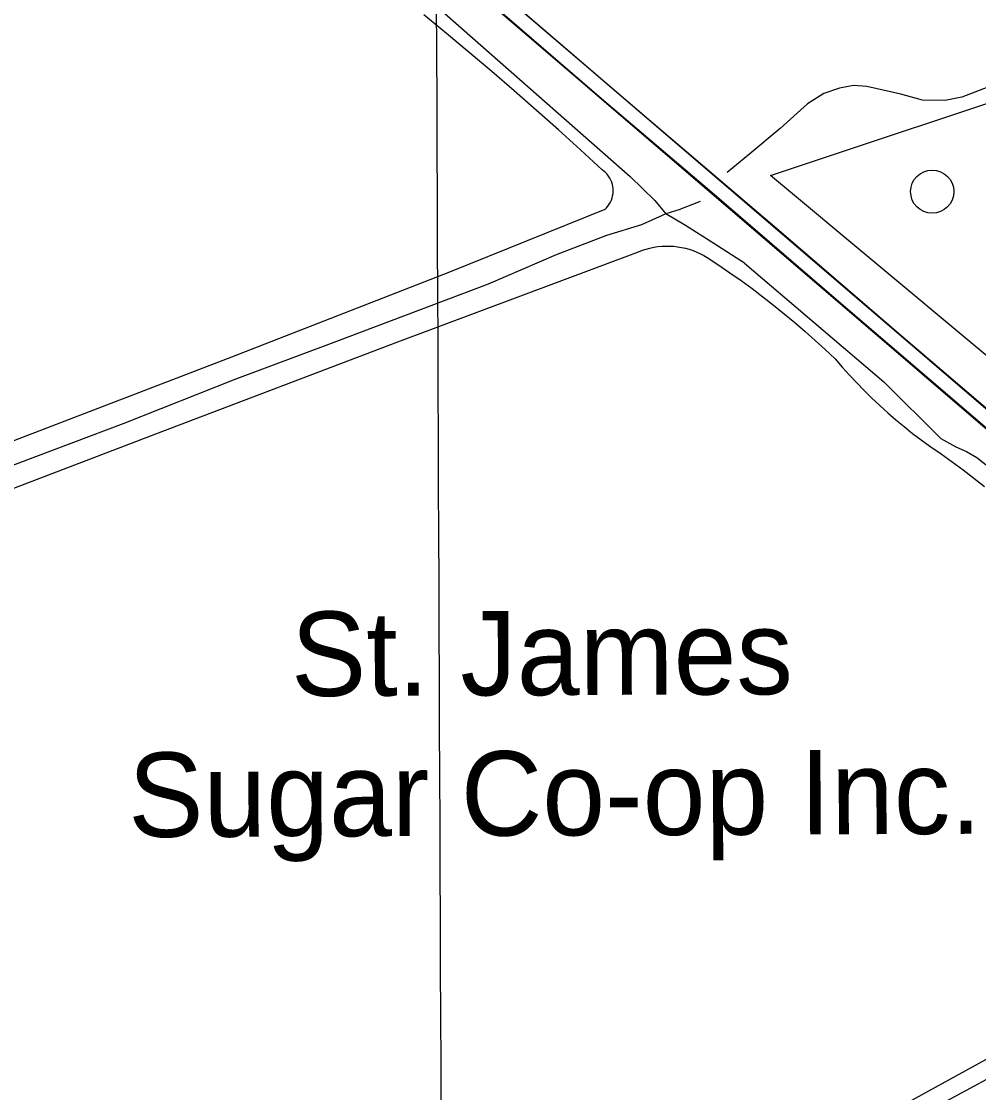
# Model space of a CAD drawing. Extents: x 3424494 to 3462436, y 522220 to 547718.
# Drawn here: x 3433422 to 3434363, y 542993 to 544046 of the extents above; entities that cross this region are included whole.
import ezdxf

# ---------------------------------------------------------------- set-up
doc = ezdxf.new("R2010")
doc.units = 0
for name, color, linetype in [('V-BLDG-IDEN', 7, 'Continuous'), ('V-DOMW-TANK', 7, 'Continuous'), ('V-DTCH-CNTR', 7, 'Continuous'), ('V-GRID-MAJR', 7, 'Continuous'), ('V-RAIL-TRAK', 7, 'Continuous'), ('V-ROAD-CNTR', 7, 'Continuous'), ('V-SITE-OTLN', 7, 'Continuous'), ('V-TOPO-SHOR', 7, 'Continuous')]:
    doc.layers.add(name, color=color, linetype=linetype)

msp = doc.modelspace()

# ---------------------------------------------------------------- linework, layer by layer
at = {"layer": 'V-DOMW-TANK'}
msp.add_circle((3434317.871326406, 543879.037215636), 21.243559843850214, dxfattribs=at)
at = {"layer": 'V-DTCH-CNTR'}
for points in [[(3433996.107, 543861.47), (3433997.694, 543863.066), (3433999.136, 543864.796), (3434000.414, 543866.652), (3434001.522, 543868.612), (3434002.448, 543870.664), (3434003.187, 543872.789), (3434003.732, 543874.975), (3434004.08, 543877.201), (3434004.225, 543879.448), (3434004.17, 543881.698), (3434003.912, 543883.935), (3434003.453, 543886.14), (3434002.8000000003, 543888.295), (3434001.9560000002, 543890.382), (3434000.928, 543892.385), (3433999.724, 543894.287), (3433998.3540000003, 543896.075), (3433996.828, 543897.732), (3433995.161, 543899.248), (3433993.365, 543900.605), (3433971.955, 543920.213), (3433950.4, 543939.665), (3433928.703, 543958.957), (3433906.865, 543978.089), (3433884.8880000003, 543997.06), (3433862.772, 544015.871), (3433840.518, 544034.518), (3433818.13, 544053.001)], [(3433996.107, 543861.47), (3433843.234, 543799.909), (3433628.991, 543716.373), (3433370.009, 543617.091)], [(3433339.258, 543558.526), (3433561.611, 543643.596), (3433792.472, 543731.187), (3434029.2660000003, 543819.929), (3434032.918, 543821.336), (3434036.639, 543822.546), (3434040.42, 543823.556), (3434044.247, 543824.365), (3434048.114, 543824.969), (3434052.005, 543825.366), (3434055.915, 543825.554), (3434059.826, 543825.536), (3434063.734, 543825.311), (3434067.6210000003, 543824.877), (3434071.482, 543824.238), (3434075.301, 543823.394), (3434079.071, 543822.3470000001), (3434082.7800000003, 543821.102), (3434086.42, 543819.66), (3434089.975, 543818.028), (3434093.438, 543816.209), (3434096.803, 543814.211), (3434107.969, 543806.825), (3434119.018, 543799.2660000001), (3434129.946, 543791.533), (3434140.751, 543783.632), (3434151.433, 543775.561), (3434161.987, 543767.322), (3434172.411, 543758.921), (3434182.7, 543750.356), (3434192.8540000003, 543741.629), (3434202.8710000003, 543732.745), (3434212.7460000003, 543723.705), (3434222.4790000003, 543714.514), (3434229.411, 543706.531), (3434236.4990000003, 543698.689), (3434243.745, 543690.991), (3434251.14, 543683.438), (3434258.687, 543676.034), (3434266.379, 543668.782), (3434274.217, 543661.688), (3434282.194, 543654.7490000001), (3434290.306, 543647.9720000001), (3434298.556, 543641.359), (3434306.934, 543634.912), (3434315.4390000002, 543628.635), (3434326.552, 543621.172), (3434337.504, 543613.474), (3434348.289, 543605.546), (3434358.906, 543597.3910000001), (3434369.347, 543589.012)], [(3434514.9620000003, 543104.937), (3434314.397, 542994.453), (3434178.242, 542919.759)]]:
    msp.add_lwpolyline(points, dxfattribs=at)
at = {"layer": 'V-GRID-MAJR'}
msp.add_spline([(3433899.984, 527634.123), (3433874.427, 533693.136), (3433848.862, 539754.083), (3433823.2970000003, 545815.045), (3433823.289, 545816.963)], degree=3, dxfattribs=at)
at = {"layer": 'V-RAIL-TRAK'}
for points in [[(3433283.139, 544579.546), (3433433.097, 544451.309), (3433542.3680000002, 544357.2710000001), (3433704.515, 544218.8910000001), (3433864.492, 544081.313), (3433992.629, 543970.577), (3434099.355, 543880.109), (3434230.64, 543767.184), (3434365.071, 543652.068), (3434485.35, 543548.884), (3434638.849, 543418.058), (3434810.4220000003, 543270.3420000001), (3434948.98, 543151.449), (3435062.972, 543054.028), (3435154.165, 542975.696)], [(3435190.421, 542962.13), (3435035.748, 543094.74), (3434892.873, 543218.593), (3434779.864, 543315.615), (3434627.745, 543445.642), (3434493.109, 543559.7710000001), (3434400.941, 543640.085), (3434291.469, 543733.728), (3434167.066, 543840.888), (3434043.438, 543946.067), (3433898.591, 544070.129), (3433740.383, 544206.314), (3433525.964, 544390.6140000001), (3433337.089, 544551.857)]]:
    msp.add_lwpolyline(points, dxfattribs=at)
at = {"layer": 'V-ROAD-CNTR'}
for points in [[(3432086.345789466, 545626.634720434), (3433017.4879271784, 544826.146321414), (3436584.012794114, 541768.2934371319), (3439656.2466496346, 539130.4327128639), (3440791.29137954, 538157.354659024)], [(3432733.0404960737, 545050.3238730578), (3433007.723946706, 544814.759344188), (3436574.245813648, 541756.9094598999), (3439266.7034287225, 539445.1300834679)]]:
    msp.add_lwpolyline(points, dxfattribs=at)
at = {"layer": 'V-SITE-OTLN'}
msp.add_lwpolyline([(3435053.9560000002, 544212.52), (3435122.661, 544125.492), (3435330.666, 543862.091), (3435410.867, 543760.518), (3435650.776, 543375.214), (3435691.986, 543311.3960000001), (3435670.5500000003, 543294.053), (3435669.788, 543293.517), (3435625.653, 543257.976), (3435228.12, 543018.135), (3434770.345, 543384.915), (3434158.997, 543894.84), (3434445.3170000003, 543990.283), (3434450.228, 543991.9130000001)], close=True, dxfattribs=at)
at = {"layer": 'V-TOPO-SHOR'}
for points in [[(3433188.427, 544626.179), (3433360.754, 544476.063), (3433710.929, 544167.03), (3434021.06, 543893.829)], [(3434430.131, 544006.831), (3434392.233, 543989.378), (3434346.938, 543971.97), (3434330.486, 543968.777), (3434308.3000000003, 543968.902), (3434286.968, 543974.778), (3434253.731, 543982.362), (3434240.5870000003, 543983.259), (3434226.603, 543980.873), (3434211.372, 543975.618), (3434195.289, 543965.439), (3434168.444, 543940.939), (3434138.719, 543916.045), (3434116.239, 543897.931)], [(3434021.06, 543893.829), (3434045.167, 543870.27), (3434055.9990000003, 543857.051)], [(3434089.758, 543869.185), (3434068.758, 543861.085), (3434055.9990000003, 543857.051), (3434032.107, 543846.503), (3433997.534, 543836.018), (3433948.122, 543816.99), (3433881.396, 543788.197), (3433729.4590000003, 543730.72), (3433632.288, 543694.294), (3433523.16, 543650.952), (3433401.284, 543605.218), (3433288.447, 543559.845), (3433171.916, 543514.901), (3433045.094, 543466.73), (3432940.877, 543419.661), (3432894.484, 543402.6900000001)], [(3434133.3310000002, 543808.8470000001), (3434103.035, 543827.92), (3434075.199, 543845.746), (3434055.9990000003, 543857.051)], [(3434133.3310000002, 543808.8470000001), (3434270.346, 543691.959), (3434326.515, 543636.332), (3434340.98, 543628.013), (3434351.546, 543623.638), (3434361.7120000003, 543617.697), (3434392.952, 543593.199), (3434744.282, 543295.047), (3434783.59, 543252.227)], [(3434789.379, 543261.015), (3434783.59, 543252.227), (3434770.312, 543232.083), (3434754.242, 543216.193), (3434708.8910000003, 543188.4400000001), (3434326.918, 542982.176), (3433969.198, 542779.895), (3433595.113, 542572.981)]]:
    msp.add_lwpolyline(points, dxfattribs=at)

# ---------------------------------------------------------------- texts
at = {"layer": 'V-BLDG-IDEN'}
for s, p in [('St. James', (3433687.5644475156, 543382.9931490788)), ('Sugar Co-op Inc.', (3433527.5346920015, 543244.3994511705))]:
    msp.add_text(s, height=82.99983200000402, rotation=0.22244718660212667, dxfattribs=at).set_placement(p)

doc.saveas('drawing.dxf')
